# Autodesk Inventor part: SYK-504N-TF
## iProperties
Company: Engineering Services Northland (1988) Ltd
Author: Malcolm
Shininess: 60.0
PropertySet Name: _Private Model Information
Created: 2001-06
Part Number: SYK-504N-TF
Material: Stainless Steel, Austenitic
Description: Plummer Block T/F Bearing, 20mm
Document SubType Name: Modeling
Designer: Malcolm
Control State: 0
Master: False
Checked Out: False
PropertySet Name: Design Tracking Control
Density: 0.0
Volumn: 0.0
Area: 0.0
PropertySet Name: Model Information
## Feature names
1. Extrusion7
2. Extrusion8
3. Extrusion9
4. Extrusion10
5. Extrusion11
6. Extrusion12
7. Fillet9
8. Fillet8
9. Fillet10
10. Revolution1
11. Hole1
12. Hole2
